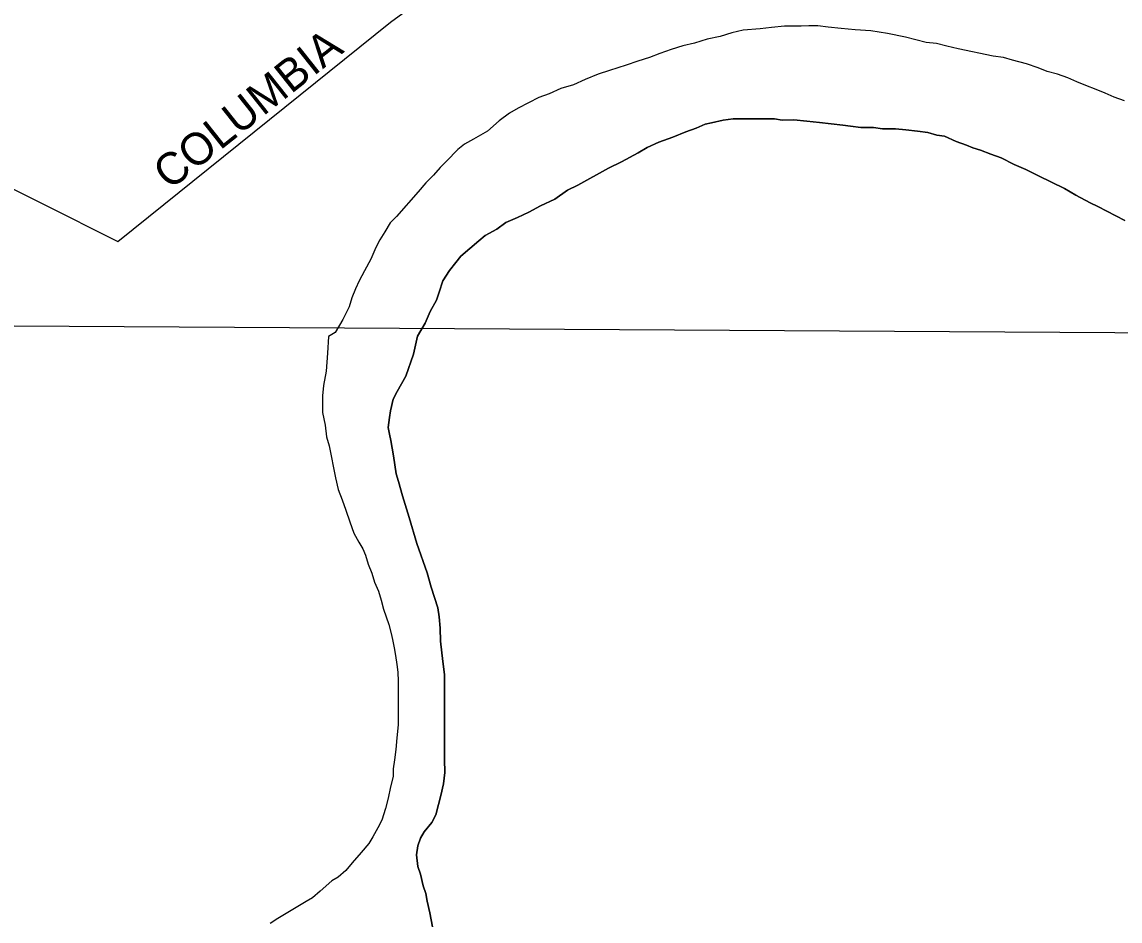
# Model space of a CAD drawing. Extents: x -561 to 1170, y 0 to 846.
# Drawn here: x 89.41 to 94.032, y 191.904 to 195.689 of the extents above; entities that cross this region are included whole.
import ezdxf

# ---------------------------------------------------------------- set-up
doc = ezdxf.new("R2010")
doc.units = 0
for name, color, linetype in [('GM_X_City_Street', 7, 'Continuous'), ('GM_X_City_Street_Text', 7, 'Continuous'), ('GM_X_Major_River', 7, 'Continuous'), ('GM_X_Township', 7, 'Continuous')]:
    doc.layers.add(name, color=color, linetype=linetype)

msp = doc.modelspace()

# ---------------------------------------------------------------- linework, layer by layer
at = {"layer": 'GM_X_City_Street'}
for points in [[(81.375, 198.237), (86.5369, 196.4531), (87.2618, 196.143), (87.7013, 195.9123), (89.1758, 195.0839), (89.8133, 194.7647)], [(89.8133, 194.7647), (90.9615, 195.6876), (92.0279, 196.467), (92.3083, 196.6967)]]:
    msp.add_lwpolyline(points, dxfattribs=at)
at = {"layer": 'GM_X_Major_River'}
for points in [[(93.7691, 195.4692), (93.7257, 195.4799), (93.6877, 195.496), (93.6389, 195.5121), (93.5792, 195.5282), (93.5412, 195.5389), (93.4979, 195.5442), (93.3515, 195.5762), (93.3027, 195.5869), (93.2593, 195.5976), (93.216, 195.6029), (93.1726, 195.6136), (93.1292, 195.6243), (93.0533, 195.6403), (92.9828, 195.6509), (92.9178, 195.6561), (92.8582, 195.6614), (92.804, 195.6666), (92.7606, 195.6719), (92.7227, 195.6718), (92.6902, 195.6716), (92.6577, 195.6716), (92.6197, 195.6714), (92.5656, 195.6658), (92.5168, 195.6603), (92.4464, 195.6546), (92.3977, 195.6437), (92.349, 195.6272), (92.2949, 195.6162), (92.2407, 195.5998), (92.192, 195.5888), (92.1433, 195.5724), (92.0946, 195.556), (92.0513, 195.5396), (92.0026, 195.5232), (91.9539, 195.5068), (91.8836, 195.4849), (91.8348, 195.4685), (91.7807, 195.4466), (91.732, 195.4248), (91.6779, 195.4084), (91.6292, 195.3866), (91.586, 195.3702), (91.5427, 195.3484), (91.4994, 195.3266), (91.4616, 195.3048), (91.4183, 195.2721), (91.3697, 195.2286), (91.3102, 195.1959), (91.2724, 195.1741), (91.2454, 195.1524), (91.1968, 195.1035), (91.1698, 195.0763), (91.1428, 195.0437), (91.1104, 195.0111), (91.078, 194.9731), (90.9863, 194.8698), (90.9593, 194.8427), (90.9377, 194.8047), (90.9162, 194.7721), (90.9001, 194.7395), (90.8786, 194.6907), (90.8516, 194.6418), (90.8301, 194.5985), (90.8139, 194.5659), (90.7979, 194.5279), (90.7871, 194.4899), (90.7602, 194.4357), (90.7279, 194.3814), (90.7009, 194.3651), (90.6957, 194.2946), (90.6905, 194.2188), (90.6799, 194.1591), (90.6746, 194.1157), (90.6748, 194.0832), (90.6749, 194.0453), (90.6859, 193.9912), (90.6915, 193.9424), (90.7025, 193.9046), (90.73, 193.7692), (90.741, 193.7204), (90.7574, 193.6772), (90.7738, 193.6339), (90.7902, 193.5852), (90.8067, 193.5365), (90.8285, 193.4986), (90.8448, 193.4716), (90.8557, 193.4445), (90.8667, 193.4066), (90.8831, 193.3687), (90.8941, 193.3309), (90.9104, 193.293), (90.9214, 193.2551), (90.9324, 193.2172), (90.9433, 193.1847), (90.9543, 193.1522), (90.9653, 193.1089), (90.9708, 193.0819), (90.9763, 193.0548), (90.9818, 193.0223), (90.9874, 192.9844)], [(93.7691, 195.4692), (93.7257, 195.4799), (93.6877, 195.496), (93.6389, 195.5121), (93.5792, 195.5282), (93.5412, 195.5389), (93.4979, 195.5442), (93.3515, 195.5762), (93.3027, 195.5869), (93.2593, 195.5976), (93.216, 195.6029), (93.1726, 195.6136), (93.1292, 195.6243), (93.0533, 195.6403), (92.9828, 195.6509), (92.9178, 195.6561), (92.8582, 195.6614), (92.804, 195.6666), (92.7606, 195.6719), (92.7227, 195.6718), (92.6902, 195.6716), (92.6577, 195.6716), (92.6197, 195.6714), (92.5656, 195.6658), (92.5168, 195.6603), (92.4464, 195.6546), (92.3977, 195.6437), (92.349, 195.6272), (92.2949, 195.6162), (92.2407, 195.5998), (92.192, 195.5888), (92.1433, 195.5724), (92.0946, 195.556), (92.0513, 195.5396), (92.0026, 195.5232), (91.9539, 195.5068), (91.8836, 195.4849), (91.8348, 195.4685), (91.7807, 195.4466), (91.732, 195.4248), (91.6779, 195.4084), (91.6292, 195.3866), (91.586, 195.3702), (91.5427, 195.3484), (91.4994, 195.3266), (91.4616, 195.3048), (91.4183, 195.2721), (91.3697, 195.2286), (91.3102, 195.1959), (91.2724, 195.1741), (91.2454, 195.1524), (91.1968, 195.1035), (91.1698, 195.0763), (91.1428, 195.0437), (91.1104, 195.0111), (91.078, 194.9731), (90.9863, 194.8698), (90.9593, 194.8427), (90.9377, 194.8047), (90.9162, 194.7721), (90.9001, 194.7395), (90.8786, 194.6907), (90.8516, 194.6418), (90.8301, 194.5985), (90.8139, 194.5659), (90.7979, 194.5279), (90.7871, 194.4899), (90.7602, 194.4357), (90.7279, 194.3814), (90.7009, 194.3651), (90.6957, 194.2946), (90.6905, 194.2188), (90.6799, 194.1591), (90.6746, 194.1157), (90.6748, 194.0832), (90.6749, 194.0453), (90.6859, 193.9912), (90.6915, 193.9424), (90.7025, 193.9046), (90.73, 193.7692), (90.741, 193.7204), (90.7574, 193.6772), (90.7738, 193.6339), (90.7902, 193.5852), (90.8067, 193.5365), (90.8285, 193.4986), (90.8448, 193.4716), (90.8557, 193.4445), (90.8667, 193.4066), (90.8831, 193.3687), (90.8941, 193.3309), (90.9104, 193.293), (90.9214, 193.2551), (90.9324, 193.2172), (90.9433, 193.1847), (90.9543, 193.1522), (90.9653, 193.1089), (90.9708, 193.0819), (90.9763, 193.0548), (90.9818, 193.0223), (90.9874, 192.9844)], [(94.0512, 195.3563), (94.0078, 195.3724), (93.9698, 195.3886), (93.9318, 195.4047), (93.8884, 195.4208), (93.8504, 195.4369), (93.8125, 195.4531), (93.7691, 195.4692)], [(94.0512, 195.3563), (94.0078, 195.3724), (93.9698, 195.3886), (93.9318, 195.4047), (93.8884, 195.4208), (93.8504, 195.4369), (93.8125, 195.4531), (93.7691, 195.4692)], [(94.0529, 194.8524), (93.9389, 194.9117), (93.9064, 194.9278), (93.8467, 194.9602), (93.7978, 194.9871), (93.7435, 195.014), (93.6893, 195.0409), (93.635, 195.0678), (93.5861, 195.0894), (93.5319, 195.1163), (93.4885, 195.1324), (93.4451, 195.1485), (93.4125, 195.1592), (93.3854, 195.17), (93.342, 195.1861), (93.2932, 195.2076), (93.2606, 195.2129), (93.2227, 195.2237), (93.1793, 195.229), (93.1305, 195.2342), (93.0872, 195.2395), (93.033, 195.2393), (92.9951, 195.2446), (92.9409, 195.2444), (92.8975, 195.2497), (92.865, 195.255), (92.8162, 195.2603), (92.7675, 195.2655), (92.7132, 195.2708), (92.659, 195.2761), (92.6103, 195.2759), (92.5778, 195.2812), (92.5507, 195.2811), (92.5127, 195.281), (92.464, 195.2809), (92.4044, 195.2807), (92.361, 195.2751), (92.3123, 195.2641), (92.2853, 195.2586), (92.2474, 195.2422), (92.2041, 195.2259), (92.15, 195.204), (92.0905, 195.1822), (92.0418, 195.1603), (92.0039, 195.1385), (91.9336, 195.1004), (91.8795, 195.0731), (91.7498, 195.0023)], [(91.7498, 195.0023), (91.8795, 195.0731), (91.9336, 195.1004), (92.0039, 195.1385), (92.0418, 195.1603), (92.0905, 195.1822), (92.15, 195.204), (92.2041, 195.2259), (92.2474, 195.2422), (92.2853, 195.2586), (92.3123, 195.2641), (92.361, 195.2751), (92.4044, 195.2807), (92.464, 195.2809), (92.5127, 195.281), (92.5507, 195.2811), (92.5778, 195.2812), (92.6103, 195.2759), (92.659, 195.2761), (92.7132, 195.2708), (92.7675, 195.2655), (92.8162, 195.2603), (92.865, 195.255), (92.8975, 195.2497), (92.9409, 195.2444), (92.9951, 195.2446), (93.033, 195.2393), (93.0872, 195.2395), (93.1305, 195.2342), (93.1793, 195.229), (93.2227, 195.2237), (93.2606, 195.2129), (93.2932, 195.2076), (93.342, 195.1861), (93.3854, 195.17), (93.4125, 195.1592), (93.4451, 195.1485), (93.4885, 195.1324), (93.5319, 195.1163), (93.5861, 195.0894), (93.635, 195.0678), (93.6893, 195.0409), (93.7435, 195.014), (93.7978, 194.9871), (93.8467, 194.9602), (93.9064, 194.9278), (93.9389, 194.9117), (94.0529, 194.8524)], [(91.7498, 195.0023), (91.7065, 194.9805), (91.6524, 194.9424), (91.593, 194.9151), (91.5443, 194.8879), (91.4956, 194.8661), (91.4469, 194.8442), (91.4091, 194.817), (91.3604, 194.7897), (91.3334, 194.768), (91.2956, 194.7353), (91.2577, 194.7027), (91.2362, 194.6756), (91.2092, 194.643), (91.1823, 194.5996), (91.1662, 194.5507), (91.1554, 194.5182), (91.1285, 194.4694), (91.107, 194.4205), (91.0747, 194.3663), (91.0587, 194.2903), (91.0265, 194.1982), (90.9888, 194.133), (90.9727, 194.1004), (90.962, 194.0516), (90.9567, 194.0245), (90.9514, 193.9812), (90.9569, 193.9541), (90.9624, 193.927), (90.968, 193.8945), (90.9735, 193.8621), (90.9791, 193.8242), (90.9846, 193.7862), (90.9956, 193.7538), (91.012, 193.6942), (91.0394, 193.6022), (91.0723, 193.4939), (91.1161, 193.3695), (91.1325, 193.3099), (91.1599, 193.2233), (91.1655, 193.1854), (91.1711, 193.1367), (91.1712, 193.0825), (91.1768, 193.0337), (91.1824, 192.985), (91.188, 192.9417), (91.1881, 192.8983), (91.1883, 192.855), (91.1884, 192.8117), (91.1886, 192.7629), (91.1887, 192.7141), (91.189, 192.66), (91.1892, 192.5841), (91.1894, 192.5299), (91.1841, 192.4811), (91.1735, 192.4324), (91.1628, 192.3944), (91.1521, 192.351), (91.136, 192.3185), (91.1036, 192.2804), (91.0874, 192.2533), (91.0767, 192.2208), (91.0714, 192.1828), (91.077, 192.1341), (91.0879, 192.1016), (91.0989, 192.0529), (91.1099, 192.0204), (91.1154, 191.9879), (91.1264, 191.9392), (91.1375, 191.8796)], [(91.1375, 191.8796), (91.1264, 191.9392), (91.1154, 191.9879), (91.1099, 192.0204), (91.0989, 192.0529), (91.0879, 192.1016), (91.077, 192.1341), (91.0714, 192.1828), (91.0767, 192.2208), (91.0874, 192.2533), (91.1036, 192.2804), (91.136, 192.3185), (91.1521, 192.351), (91.1628, 192.3944), (91.1735, 192.4324), (91.1841, 192.4811), (91.1894, 192.5299), (91.1892, 192.5841), (91.189, 192.66), (91.1887, 192.7141), (91.1886, 192.7629), (91.1884, 192.8117), (91.1883, 192.855), (91.1881, 192.8983), (91.188, 192.9417), (91.1824, 192.985), (91.1768, 193.0337), (91.1712, 193.0825), (91.1711, 193.1367), (91.1655, 193.1854), (91.1599, 193.2233), (91.1325, 193.3099), (91.1161, 193.3695), (91.0723, 193.4939), (91.0394, 193.6022), (91.012, 193.6942), (90.9956, 193.7538), (90.9846, 193.7862), (90.9791, 193.8242), (90.9735, 193.8621), (90.968, 193.8945), (90.9624, 193.927), (90.9569, 193.9541), (90.9514, 193.9812), (90.9567, 194.0245), (90.962, 194.0516), (90.9727, 194.1004), (90.9888, 194.133), (91.0265, 194.1982), (91.0587, 194.2903), (91.0747, 194.3663), (91.107, 194.4205), (91.1285, 194.4694), (91.1554, 194.5182), (91.1662, 194.5507), (91.1823, 194.5996), (91.2092, 194.643), (91.2362, 194.6756), (91.2577, 194.7027), (91.2956, 194.7353), (91.3334, 194.768), (91.3604, 194.7897), (91.4091, 194.817), (91.4469, 194.8442), (91.4956, 194.8661), (91.5443, 194.8879), (91.593, 194.9151), (91.6524, 194.9424), (91.7065, 194.9805), (91.7498, 195.0023)], [(90.9874, 192.9844), (90.9929, 192.9519), (90.993, 192.914), (90.9932, 192.8598), (90.9934, 192.8165), (90.9935, 192.7731), (90.9936, 192.7298), (90.9884, 192.6756), (90.9832, 192.6268), (90.9779, 192.5834), (90.9726, 192.5455), (90.9727, 192.513), (90.962, 192.4696), (90.9514, 192.4208), (90.9407, 192.3774), (90.9246, 192.3286), (90.9084, 192.2961), (90.8869, 192.2581), (90.8708, 192.2309), (90.8384, 192.1929), (90.8006, 192.1494), (90.7736, 192.1168), (90.7412, 192.0896), (90.7142, 192.0733), (90.6656, 192.0298), (90.6332, 192.0026), (90.6061, 191.9863), (90.4872, 191.9155), (90.4547, 191.8937)], [(90.9874, 192.9844), (90.9929, 192.9519), (90.993, 192.914), (90.9932, 192.8598), (90.9934, 192.8165), (90.9935, 192.7731), (90.9936, 192.7298), (90.9884, 192.6756), (90.9832, 192.6268), (90.9779, 192.5834), (90.9726, 192.5455), (90.9727, 192.513), (90.962, 192.4696), (90.9514, 192.4208), (90.9407, 192.3774), (90.9246, 192.3286), (90.9084, 192.2961), (90.8869, 192.2581), (90.8708, 192.2309), (90.8384, 192.1929), (90.8006, 192.1494), (90.7736, 192.1168), (90.7412, 192.0896), (90.7142, 192.0733), (90.6656, 192.0298), (90.6332, 192.0026), (90.6061, 191.9863), (90.4872, 191.9155), (90.4547, 191.8937)]]:
    msp.add_lwpolyline(points, dxfattribs=at)
at = {"layer": 'GM_X_Township'}
msp.add_lwpolyline([(74.3125, 189.1839), (86.8265, 189.1154), (88.7634, 189.1048), (88.6817, 194.4134), (94.9365, 194.3754), (104.1165, 194.3195)], dxfattribs=at)

# ---------------------------------------------------------------- texts
at = {"layer": 'GM_X_City_Street_Text'}
msp.add_text('COLUMBIA', height=0.135, rotation=38.4186, dxfattribs=at).set_placement((90.0318, 194.9784))

doc.saveas('drawing.dxf')
